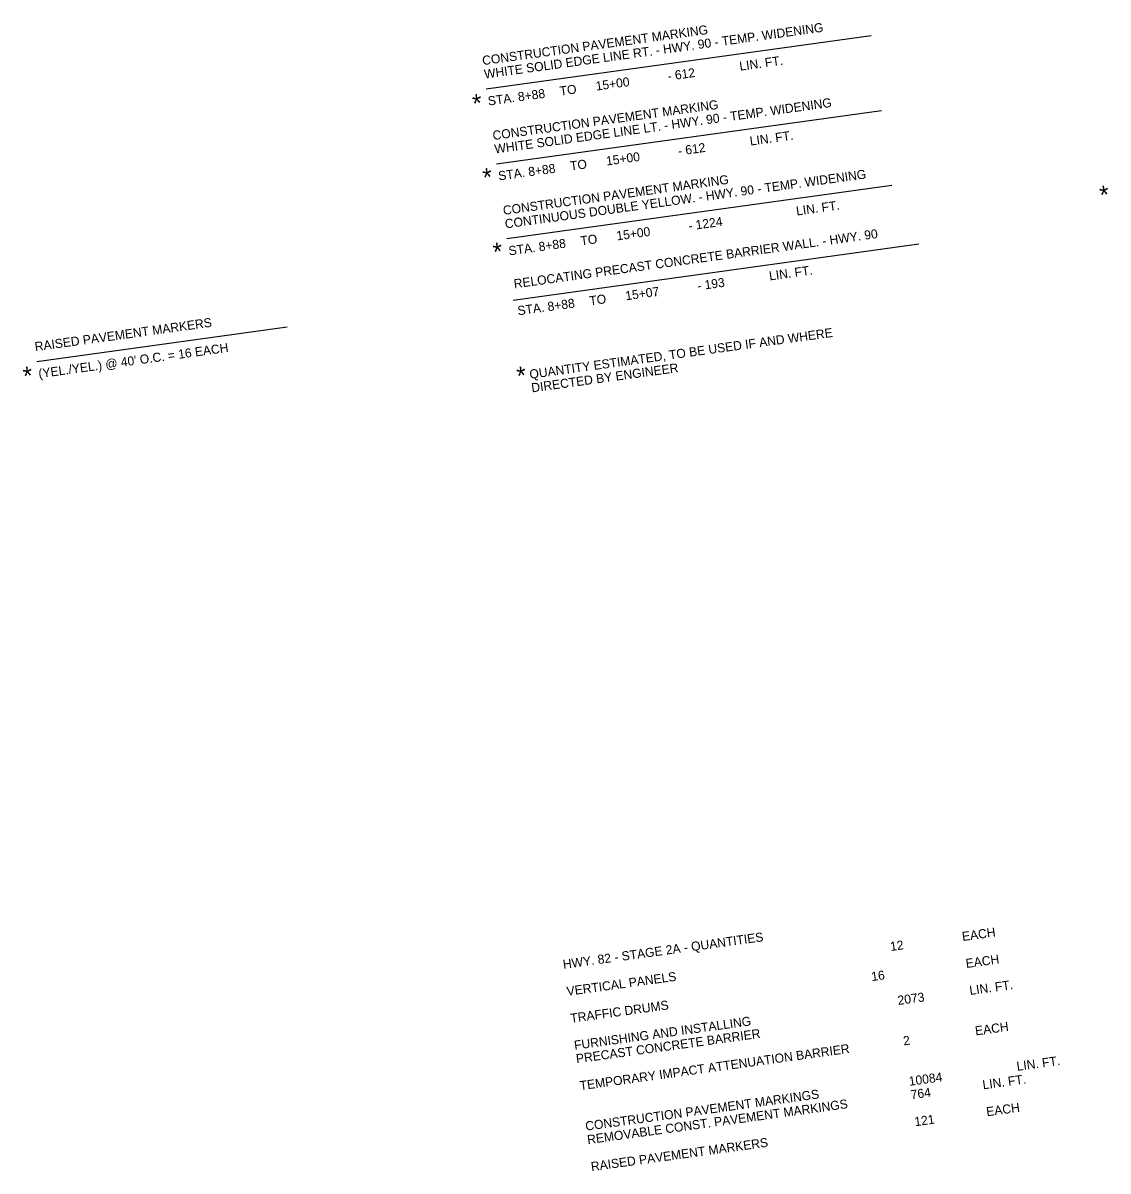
# Model space of a CAD drawing. Extents: x 1567994 to 1569894, y 731119 to 732494.
# Drawn here: x 1567994 to 1568711, y 731119 to 731878 of the extents above; entities that cross this region are included whole.
import ezdxf

# ---------------------------------------------------------------- set-up
doc = ezdxf.new("R2010")
doc.units = 0
doc.layers.add('R_Annotation', color=7, linetype='Continuous')

msp = doc.modelspace()

# ---------------------------------------------------------------- linework, layer by layer
at = {"layer": 'R_Annotation'}
for p, q in [((1568300.1, 731834.42), (1568554.7, 731869.72)), ((1568306.97, 731784.9), (1568561.57, 731820.19)), ((1568313.83, 731735.37), (1568568.43, 731770.67)), ((1568317.91, 731694.64), (1568586.22, 731731.84)), ((1568002.86, 731654.2), (1568168.41, 731677.15))]:
    msp.add_line(p, q, dxfattribs=at)

# ---------------------------------------------------------------- texts
for s, height, p in [('CONSTRUCTION PAVEMENT MARKING', 6, (1568297.93, 731850.07)), ('WHITE SOLID EDGE LINE RT. - HWY. 90 - TEMP. WIDENING', 6, (1568299.17, 731841.16)), ('LIN. FT.', 6, (1568468.05, 731846.4)), ('- 612', 6, (1568420.5, 731839.81)), ('TO', 6, (1568349.18, 731829.92)), ('15+00', 6, (1568372.96, 731833.21)), ('*', 12, (1568291.97, 731818.58)), ('STA. 8+88', 6, (1568301.64, 731823.33)), ('WHITE SOLID EDGE LINE LT. - HWY. 90 - TEMP. WIDENING', 6, (1568306.03, 731791.63)), ('CONSTRUCTION PAVEMENT MARKING', 6, (1568304.8, 731800.55)), ('LIN. FT.', 6, (1568474.91, 731796.87)), ('- 612', 6, (1568427.37, 731790.28)), ('15+00', 6, (1568379.82, 731783.69)), ('*', 12, (1568298.75, 731769.67)), ('STA. 8+88', 6, (1568308.5, 731773.8)), ('TO', 6, (1568356.05, 731780.39)), ('CONSTRUCTION PAVEMENT MARKING', 6, (1568311.66, 731751.02)), ('CONTINUOUS DOUBLE YELLOW. - HWY. 90 - TEMP. WIDENING', 6, (1568312.9, 731742.1)), ('*', 12, (1568706.78, 731758.06)), ('LIN. FT.', 6, (1568505.55, 731750.64)), ('- 1224', 6, (1568434.23, 731740.75)), ('RELOCATING PRECAST CONCRETE BARRIER WALL. - HWY. 90', 6, (1568318.79, 731702.48)), ('TO', 6, (1568362.92, 731730.87)), ('15+00', 6, (1568386.69, 731734.16)), ('*', 12, (1568305.56, 731720.49)), ('STA. 8+88', 6, (1568315.37, 731724.27)), ('LIN. FT.', 6, (1568487.67, 731707.72)), ('- 193', 6, (1568440.12, 731701.13)), ('TO', 6, (1568368.8, 731691.24)), ('15+07', 6, (1568392.58, 731694.54)), ('STA. 8+88', 6, (1568321.26, 731684.65)), ('RAISED PAVEMENT MARKERS', 6, (1568001.93, 731660.93)), ('QUANTITY ESTIMATED, TO BE USED IF AND WHERE', 6, (1568329.18, 731642.64)), ("(YEL./YEL.) @ 40' O.C. = 16 EACH", 6, (1568004.4, 731643.1)), ('DIRECTED BY ENGINEER', 6, (1568330.42, 731633.72)), ('*', 12, (1567994.72, 731638.37)), ('*', 12, (1568321.23, 731638.48)), ('HWY. 82 - STAGE 2A - QUANTITIES', 6, (1568351.3, 731252.5)), ('EACH', 6, (1568615.27, 731270.92)), ('12', 6, (1568567.72, 731264.33)), ('EACH', 6, (1568617.74, 731253.09)), ('VERTICAL PANELS ', 6, (1568353.77, 731234.67)), ('    16', 6, (1568546.42, 731243.21)), ('LIN. FT.', 6, (1568620.21, 731235.27)), ('2073', 6, (1568572.66, 731228.67)), ('TRAFFIC DRUMS', 6, (1568356.24, 731216.84)), ('FURNISHING AND INSTALLING', 6, (1568358.71, 731199.01)), ('PRECAST CONCRETE BARRIER', 6, (1568359.95, 731190.1)), ('EACH', 6, (1568623.92, 731208.52)), ('2', 6, (1568576.37, 731201.93)), ('TEMPORARY IMPACT ATTENUATION BARRIER', 6, (1568362.42, 731172.27)), ('LIN. FT.', 6, (1568651.4, 731185.07)), ('10084', 6, (1568580.08, 731175.19)), ('LIN. FT.', 6, (1568628.86, 731172.86)), ('CONSTRUCTION PAVEMENT MARKINGS', 6, (1568366.13, 731145.52)), ('764 ', 6, (1568581.32, 731166.27)), ('REMOVABLE CONST. PAVEMENT MARKINGS ', 6, (1568367.36, 731136.61)), ('EACH', 6, (1568631.33, 731155.03)), ('121', 6, (1568583.79, 731148.44)), ('RAISED PAVEMENT MARKERS', 6, (1568369.83, 731118.78))]:
    msp.add_text(s, height=height, rotation=7.89288, dxfattribs=at).set_placement(p)

doc.saveas('drawing.dxf')
